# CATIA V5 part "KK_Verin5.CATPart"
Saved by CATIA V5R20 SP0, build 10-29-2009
Part number: Verin5
Bounding box of the stored display mesh (mm): x -54.705 to -40.504, y -91.762 to -57.245, z -5 to 66.399
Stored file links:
  G:\Khaled_CFAO_2011\ST2M\ST2M_GR1\msallin\Khaled\Version_Finale\KK_Verin5.CATPart
  C:\Users\Mathieu\Desktop\Think Motion\JOUG-MELEE2.CATProduct
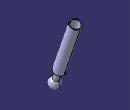
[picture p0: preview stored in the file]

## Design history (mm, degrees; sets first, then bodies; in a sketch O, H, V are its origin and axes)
External parameters (linked from other documents)
  `External.Taille du joug` = 100 mm
Set1
  Line1: linked copy from another document
  Line2: linked copy from another document
  Point1: linked copy from another document
Set2
  Plane1: type 2Lines, Element1 Line1, Element2 Line2
  Plane2: type 2Lines, Element1 Sketch1.L3, Element2 Sketch1.L5
  Point2: type Center, Curve Sketch1
  DatumSurface1
Body1 (main body)
  Sketch1 on Plane1, origin (-70.4493, -40.9938, 20.3771), H (0.5029, -0.8643, 0), V (0.2096, 0.122, 0.9701)
    line L1 (51.1904, -16.148) -> (48.3959, -6.5464)
    line L2 (48.3959, -6.5464) -> (50.7963, -5.8477)
    line L3 (50.7963, -5.8477) -> (35.4266, 46.9611)
    line L4 (35.4266, 46.9611) -> (34.6265, 46.7282)
    line L5 (34.6265, 46.7282) -> (46.9222, 4.4812)
    line L6 (46.9222, 4.4812) -> (42.9216, 3.3168)
    point P7 (42.9216, 3.3168)
    arc A1 centre (50, -21.0042) radius 5 from (51.3972, -25.805) to (51.1904, -16.148) ccw
    point P8 (50, -21.0042)
    point P9 (51.3972, -25.805)
    reference projected line E1 (20, 82.0734) -> (50, -21.0042) from Line2
    reference projected line E2 (20, 82.0734) -> (50, -21.0042) from Line2
    reference projected line E3 (20, 82.0734) -> (50, -21.0042) from Line2
    reference projected point E4 (50, -21.0042) from Point1
    reference projected line E5 (20, 82.0734) -> (50, -21.0042) from Line2
    length L3 = 55 {= `External.Taille du joug` *(7/10-1/10-1/20)}
    length L5 = 44 {= Sketch1.length(L3) *4/5}
    distance L3 E1 = 5 {= `External.Taille du joug` /20}
    distance L5 E2 = 4.1667 {= `External.Taille du joug` /24}
    length L1 = 10 {= `External.Taille du joug` /10}
    distance P7 E3 = 0
    length L2 = 2.5 {= `External.Taille du joug` /40}
    radius A1 = 5 {= `External.Taille du joug` /20}
    distance P8 E4 = 0
    distance P9 E5 = 0
    perpendicularity: L2 L1
    parallelism: L3 L1, L4 L2, L5 L3, L6 L2
  Shaft1: profile Sketch1, axis Line2, angle 360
